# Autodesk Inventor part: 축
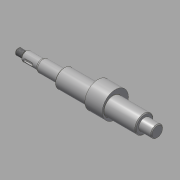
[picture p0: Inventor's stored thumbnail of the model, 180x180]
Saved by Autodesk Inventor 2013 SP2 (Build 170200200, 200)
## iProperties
Created: 2015-12
Part Number: 축
Document SubType Name: Modeling
Designer: mdu
Density: 7.86 g/cm^3
Material: 강철, 연강
Author: mdu
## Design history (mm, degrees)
sketch "스케치1"
  geometry: L1 (62, 100.9)-(62, 67.1) reference; L2 (51, 101.2)-(51, 84) reference; L3 (-51, 84)-(-51, 101.2) reference; L4 (-62, 67.1)-(-62, 100.9) reference; L5 (-51.6, 91.5)-(-61.4, 91.5) reference; L6 (51.6, 91.5)-(61.4, 91.5) reference; L7 (67, 84)-(-109, 84); L8 (-77, 64.201)-(-77, 103.799) reference; L9 (67, 84)-(67, 91.5); L10 (67, 91.5)-(51, 91.5); L11 (51, 91.5)-(51, 95.5); L12 (51, 95.5)-(-51, 95.5); L13 (-51, 95.5)-(-51, 91.5); L14 (-51, 91.5)-(-79, 91.5); L15 (-79, 91.5)-(-79, 90); L16 (-79, 90)-(-99, 90); L17 (-99, 90)-(-99, 87); L18 (-100.5, 88)-(-109, 88); L19 (-109, 88)-(-109, 84); L20 (-99, 87)-(-100.5, 87); L21 (-100.5, 87)-(-100.5, 88); 2 further points
  constraints: 32 end point, 7 parallel, 6 point on line, 5 perpendicular, 2 collinear, 2 horizontal, 1 midpoint, 4 other
  dimensions: "d0" = 5 distance from line of L7.start L1; "d2" = 2 distance between parallel lines of L15 L8; "d3" = 23 diameter of L12 L7; "d4" = 12 diameter of L16 L7; "d5" = 1.5 distance of L17.end L20.end; "d6" = 6 diameter of L20 L7; "d7" = 20 distance of L15.end L16.end; "d8" = 10 distance between parallel lines of L17 L19; "d9" = 8 diameter of L18 L7
revolve "회전1" sketch "스케치1" stored, may be unused: angle "d10" = 90 deg
sketch "스케치2"
  geometry: C1 r 11.5 at (84, 0) reference; C2 r 11.5 at (84, 0) reference; C3 r 16.5 at (87, 0); 1 further point
  constraints: 1 centre point, 1 horizontal alignment
  dimensions: "d11" = 33 diameter of C3; "d12" = 3 distance of C3.centre C1.centre
extrude "돌출1" join sketch "스케치2" stored distance "d13" = 22; taper "d14" = 0 deg
chamfer "모따기1" distance "d15" = 1; stored, may be unused: second distance "d16" = 2, angle "d17" = 45 deg
feature "스레드1" dims "d18" = 10, "d19" = 0
node "작업 평면1"
sketch "스케치3"
  geometry: L1 (-5, -2)-(3, -2); L2 (3, 2)-(-5, 2); L3 (-10, -5)-(-10, 5) reference; A1 r 2 centre (3, 0) between (3, -2) and (3, 2); A2 r 2 centre (-5, 0) between (-5, 2) and (-5, -2); 2 further points
  constraints: 4 end point, 4 point on circle, 4 tangent, 2 centre point, 1 horizontal, 1 horizontal alignment, 1 midpoint, 1 parallel
  dimensions: "d20" = 4 distance between parallel lines of L1 L2; "d21" = 12 dimension on A1 A2; "d22" = 3 distance edge to line of A2 L3
extrude "돌출2" cut sketch "스케치3" distance "d23" = 2.5; taper "d24" = 0 deg
fillet "모깎기1" dims "d25" = 0.3
fillet "모깎기2" dims "d26" = 3
node "솔리드1"
node "참조1"
node "참조2"
node "참조3"
node "참조4"
node "참조5"
node "투영된 루프1"
